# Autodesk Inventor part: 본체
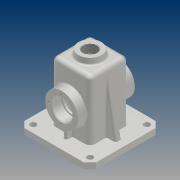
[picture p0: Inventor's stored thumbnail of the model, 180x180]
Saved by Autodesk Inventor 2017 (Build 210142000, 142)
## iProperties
Part Number: 본체
Material: 알루미늄 6061
Document SubType Name: Modeling
Designer: 20
Density: 2.7 g/cm^3
Appearance: 알루미늄 - 평지
Mass: 788.71 g
Surface Area: 897.365 cm^2
Volume: 292.115 cm^3
Author: 20
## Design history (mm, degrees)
sketch "스케치2"
  geometry: L1 (-32.5, 32.5)-(32.5, 32.5); L2 (32.5, 32.5)-(32.5, -32.5); L3 (32.5, -32.5)-(-32.5, -32.5); L4 (-32.5, -32.5)-(-32.5, 32.5); L5 (-32.5, 32.5)-(32.5, -32.5); L6 (32.5, 32.5)-(-32.5, -32.5); 1 further point
  constraints: 12 end point, 2 midpoint, 2 parallel, 1 horizontal, 1 perpendicular
  dimensions: "d2" = 65 distance of L1.start L1.end; "d3" = 65 distance of L1.end L2.end
extrude "돌출1" new body sketch "스케치2" distance "d4" = 110; taper "d5" = 0 deg
sketch "스케치4"
  geometry: L1 (32.5, 0)-(-32.5, 0) reference; L2 (27.5, 0)-(-27.5, 0); L3 (-27.5, 0)-(-27.5, 105); L4 (-27.5, 105)-(27.5, 105); L5 (27.5, 105)-(27.5, 0); L6 (0, 105)-(0, 0); 2 further points
  constraints: 10 end point, 3 midpoint, 2 parallel, 2 point on line, 1 horizontal, 1 perpendicular
  dimensions: "d10" = 105 distance of L2.end L3.end; "d11" = 55 distance of L3.end L4.end
extrude "돌출3" cut sketch "스케치4" stored distance "d12" = 55; taper "d13" = 0 deg
sketch "스케치5"
  geometry: L1 (-60, -60)-(60, -60); L2 (60, -60)-(60, 60); L3 (60, 60)-(-60, 60); L4 (-60, 60)-(-60, -60); L5 (-60, -60)-(60, 60); L6 (60, -60)-(-60, 60); L7 (-27.5, 27.5)-(-27.5, -27.5) reference; L8 (-27.5, -27.5)-(27.5, -27.5) reference; L9 (27.5, 27.5)-(27.5, -27.5) reference; L10 (27.5, 27.5)-(-27.5, 27.5) reference; 1 further point
  constraints: 12 end point, 2 midpoint, 2 parallel, 1 horizontal, 1 perpendicular
  dimensions: "d14" = 120 distance of L3.end L1.start; "d15" = 120 distance of L2.end L3.end
extrude "돌출4" join sketch "스케치5" distance "d16" = 10; taper "d17" = 0 deg
sketch "스케치6"
  geometry: L1 (92.5, -110)-(-27.5, -110) reference; C1 r 27.5 at (32.5, -55); 2 further points
  constraints: 1 centre point, 1 midpoint, 1 vertical alignment
  dimensions: "d18" = 55 diameter of C1; "d19" = 55 distance from line of C1.centre L1
extrude "돌출5" join sketch "스케치6" distance "d20" = 15; taper "d21" = 0 deg
fillet "모깎기1" dims "d22" = 8
fillet "모깎기2" dims "d23" = 8
fillet "모깎기3" dims "d24" = 3
fillet "모깎기4" dims "d25" = 3
sketch "스케치7"
  geometry: C1 r 17.5 at (0, 0); C2 r 27.5 at (0, 0) reference; 1 further point
  constraints: 1 centre point, 1 concentric
  dimensions: "d26" = 35 diameter of C1
extrude "돌출6" cut sketch "스케치7" distance "d27" = 17; taper "d28" = 0 deg
sketch "스케치8"
  geometry: C1 r 15 at (0, 0); C2 r 17.5 at (0, 0) reference; 1 further point
  constraints: 1 centre point, 1 concentric
  dimensions: "d29" = 30 diameter of C1
extrude "돌출7" cut sketch "스케치8" stored distance "d30" = 17; taper "d31" = 0 deg
sketch "스케치9"
  geometry: C1 r 20 at (0, 0); 1 further point
  constraints: 1 centre point, 1 coincident
  dimensions: "d32" = 40 diameter of C1
extrude "돌출8" join sketch "스케치9" distance "d33" = 10; taper "d34" = -5 deg
hole "구멍1" diameter "d37" = 22.835; stored, may be unused: countersink angle "d41" = 90 deg, drill point angle "d43" = 118 deg; dims "d35" = 10, "d36" = 10, "d38" = 50, "d39" = 4, "d40" = 2, "d42" = 59.3
sketch "스케치11"
  geometry: L1 (60, -55)-(-60, -55) reference; C1 r 27.5 at (0, 0) reference; 3 further points
  constraints: 1 midpoint, 1 vertical alignment
  dimensions: "d44" = 21 distance of point (0, 21) C1.centre
hole "구멍2" sketch "스케치11" at (0, 21) diameter "d45" = 3.242; stored, may be unused: countersink angle "d49" = 90 deg, drill point angle "d51" = 118 deg; dims "d46" = 8, "d47" = 4, "d48" = 2, "d50" = 10
chamfer "모따기1" distance "d55" = 1; stored, may be unused: second distance "d56" = 2, angle "d57" = 45 deg
fillet "모깎기5" dims "d58" = 3
chamfer "모따기2" distance "d60" = 10; stored, may be unused: second distance "d61" = 2, angle "d62" = 45 deg
sketch "스케치12"
  geometry: L1 (-50, -60)-(50, -60) reference; L2 (60, -50)-(60, 50) reference; C1 r 5 at (47.5, -47.5); 1 further point
  constraints: 1 centre point
  dimensions: "d63" = 10 diameter of C1; "d64" = 12.5 distance from line of L1 C1.centre; "d65" = 12.5 distance from line of L2 C1.centre
extrude "돌출9" cut sketch "스케치12" stored distance "d66" = 10; taper "d67" = 0 deg
sketch "스케치13"
  geometry: L1 (-40.065, 55)-(-48, 10); L2 (-50, 10)-(-60, 10) reference; L3 (-60, 10)-(-60, 0) reference; 1 further point
  constraints: 2 end point, 1 point on line
  dimensions: "d74" = 12 distance from line of L3 L1.end; "d75" = 10 deg angle of L3 L1; "d76" = 45 distance from line of L2 L1.start
feature "리브1" sketch "스케치13" dims "d77" = 1, "d78" = 10, "d79" = 0, "d80" = 0, "d81" = 1, "d82" = 1
sketch "스케치14"
  geometry: L1 (-24.5, -27.5)-(24.5, -27.5) reference; L2 (-3, -27.5)-(3, -27.5); L3 (3, -27.5)-(3, -42.5); L4 (3, -42.5)-(-3, -42.5); L5 (-3, -42.5)-(-3, -27.5); L6 (0, -42.5)-(0, -27.5); 1 further point
  constraints: 10 end point, 2 midpoint, 2 parallel, 2 point on line, 1 horizontal, 1 perpendicular
  dimensions: "d83" = 6 distance of L3.end L4.end; "d84" = 15 distance of L2.end L3.end
extrude "돌출10" join sketch "스케치14" stored distance "d85" = 10; taper "d86" = 0 deg
fillet "모깎기7" dims "d87" = 3
fillet "모깎기8" dims "d88" = 3
fillet "모깎기9" dims "d89" = 3
fillet "모깎기10" dims "d90" = 3
fillet "모깎기11" dims "d91" = 3
fillet "모깎기12" dims "d92" = 1
node "작업 평면1"
sketch "스케치16"
  geometry: L1 (57, 0)-(57, 91) reference; L2 (43.625, -18)-(5.375, -18) reference; 2 further points
  constraints: 1 other
  dimensions: "d94" = 32.5 distance from line of L1 point (24.5, 8); "d95" = 26 distance from line of L2 point (24.5, 8)
feature "엠보싱1" sketch "스케치16" dims "d96" = 0.5, "d97" = 0
fillet "모깎기13" dims "d98" = 0.3
node "솔리드1"
mirror "미러1"
mirror "미러2"
pattern_circular "원형 패턴1" dims angle "d53" = 360 deg
mirror "미러3"
pattern_linear "직사각형 패턴1" dims "d70" = 95, "d73" = 95
mirror "미러4"
mirror "미러5"
node "투영된 루프1"
other parameters: "d93" = 64.25
